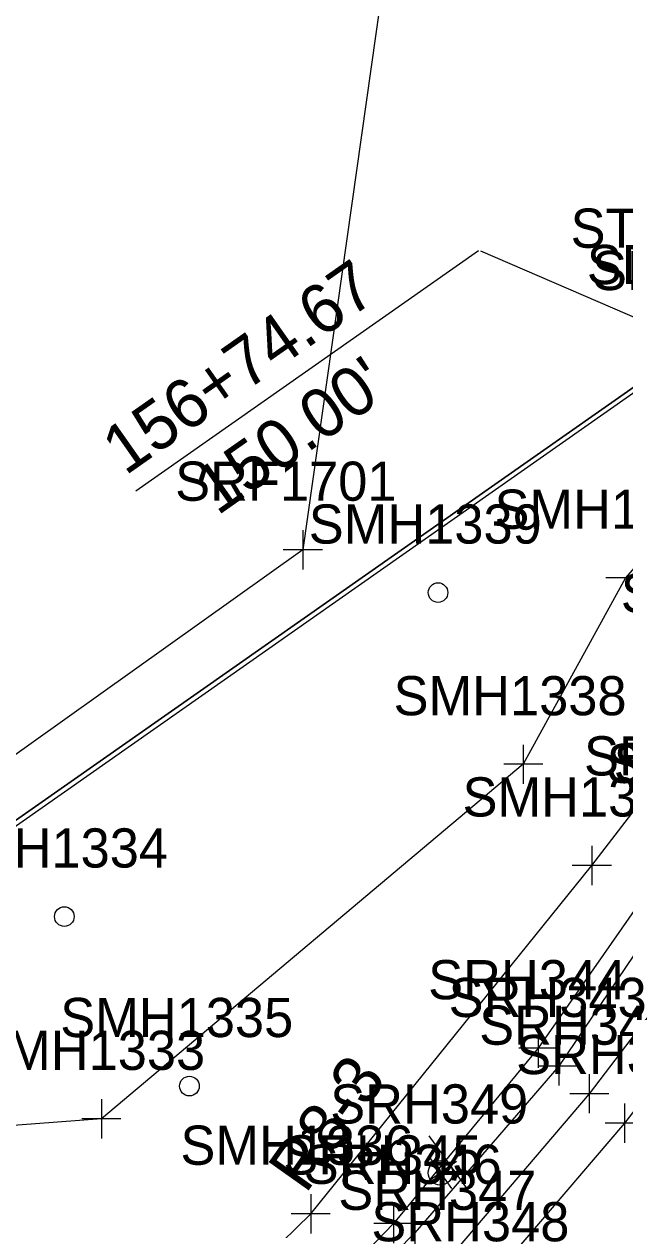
# Model space of a CAD drawing. Extents: x 941041 to 969446, y 397014 to 416764.
# Drawn here: x 951336.1 to 951397.4, y 403015.6 to 403138.7 of the extents above; entities that cross this region are included whole.
import ezdxf

# ---------------------------------------------------------------- set-up
doc = ezdxf.new("R2010")
doc.units = 0
for name, color, linetype in [('SURVEY - DRAINAGE - Area Shapes', 7, 'Continuous'), ('SURVEY - DRAINAGE - Area Shapes - Points - Locators', 7, 'Continuous'), ('SURVEY - DRAINAGE - Area Shapes - Points - Numbers', 7, 'Continuous'), ('SURVEY - DTM - Breaklines', 7, 'Continuous'), ('SURVEY - DTM - Breaklines - Points - Locators', 7, 'Continuous'), ('SURVEY - DTM - Breaklines - Points - Numbers', 7, 'Continuous'), ('SURVEY - DTM - Spot Points - Locators', 7, 'Continuous'), ('SURVEY - DTM - Spot Points - Point Numbers', 7, 'Continuous'), ('SURVEY - DTM GRAPHICS - Boundary Line', 7, 'Continuous'), ('SURVEY - NON-TRANSPORTATION - Features', 7, 'Continuous'), ('SURVEY - NON-TRANSPORTATION - Features - Points - Numbers', 7, 'Continuous'), ('SURVEY - PROPERTY - ROW Lines', 7, 'Continuous'), ('SURVEY - PROPERTY - ROW Markers - Points - Numbers', 7, 'Continuous'), ('SURVEY - PROPERTY - Station and Offset Flags', 7, 'Continuous'), ('SURVEY - TRAFFIC CONTROL - Pavement Marking - Points - Locators', 7, 'Continuous'), ('SURVEY - TRAFFIC CONTROL - Pavement Marking - Points - Numbers', 7, 'Continuous'), ('SURVEY - TRAFFIC CONTROL - Signs - Points - Locators', 7, 'Continuous'), ('SURVEY - TRAFFIC CONTROL - Signs - Points - Numbers', 7, 'Continuous'), ('SURVEY - TRAFFIC CONTROL - Signs and Devices with Text', 7, 'Continuous'), ('SURVEY - TRANSPORTATION - Features', 7, 'Continuous'), ('SURVEY - TRANSPORTATION - Features - Points - Locators', 7, 'Continuous'), ('SURVEY - TRANSPORTATION - Features - Points - Numbers', 7, 'Continuous'), ('SURVEY - TRANSPORTATION - Roads', 7, 'Continuous'), ('SURVEY - TRANSPORTATION - Roads - Points - Locators', 7, 'Continuous'), ('SURVEY - TRANSPORTATION - Roads - Points - Numbers', 7, 'Continuous'), ('SURVEY - UTILITIES - Poles and Miscellaneous - Points - Numbers', 7, 'Continuous'), ('SURVEY - VEGETATION - Features - Points - Locators', 7, 'Continuous'), ('SURVEY - VEGETATION - Features - Points - Numbers', 7, 'Continuous'), ('SURVEY - VEGETATION - Features with Text', 7, 'Continuous')]:
    doc.layers.add(name, color=color, linetype=linetype)

msp = doc.modelspace()

# ---------------------------------------------------------------- linework, layer by layer
at = {"layer": 'SURVEY - DRAINAGE - Area Shapes'}
for points in [[(951570.1, 403333.86), (951394.91, 403299.54), (951364.56, 403085.05), (950690.3, 402604.57), (950747.14, 402539.76)], [(950765.73, 402528.11), (951145.6, 402792.15), (951242.57, 402873.52), (951348.31, 402952.21), (951398.95, 403004.27), (951428.85, 403040.93), (951473.12, 403113.97), (951570.1, 403333.86), (951394.91, 403299.54), (951364.56, 403085.05), (950690.3, 402604.57), (950747.14, 402539.76), (950765.73, 402528.11)]]:
    msp.add_lwpolyline(points, dxfattribs=at)
at = {"layer": 'SURVEY - DRAINAGE - Area Shapes - Points - Locators'}
for p, q in [((951364.56, 403087.05), (951364.56, 403083.05)), ((951366.56, 403085.05), (951362.56, 403085.05))]:
    msp.add_line(p, q, dxfattribs=at)
at = {"layer": 'SURVEY - DTM - Breaklines'}
for points in [[(950944.44, 402708.35), (950986.6, 402737.09), (951031.98, 402767.67), (951074.18, 402796.92), (951116.54, 402825.71), (951158.8, 402855.37), (951201.22, 402884.32), (951244.36, 402916.65), (951286.66, 402946.54), (951324.24, 402977.13), (951365.36, 403017.29), (951394.06, 403052.83), (951410.05, 403073.63), (951458.13, 403162.28), (951483.55, 403213.16), (951504.25, 403257.1), (951548.43, 403354.82)], [(951404.5, 403057.02), (951388.59, 403034.18), (951373.81, 403016.3), (951353.68, 402995.42), (951325.73, 402969.82), (951296.63, 402946.16), (951268.96, 402924.9), (951228.2, 402894.58), (951186.77, 402863.94), (951145.14, 402834.63), (951106.17, 402807.78), (951067.06, 402780.74), (951027.03, 402752.5), (950987.44, 402723.92), (950948.21, 402695.85), (950901.61, 402662.26), (950863.92, 402634.17), (950821.87, 402602.73), (950781, 402573.02)]]:
    msp.add_lwpolyline(points, dxfattribs=at)
at = {"layer": 'SURVEY - DTM - Breaklines - Points - Locators'}
for p, q in [((951394.06, 403054.83), (951394.06, 403050.83)), ((951396.06, 403052.83), (951392.06, 403052.83)), ((951388.59, 403036.18), (951388.59, 403032.18)), ((951390.59, 403034.18), (951386.59, 403034.18)), ((951365.36, 403019.29), (951365.36, 403015.29)), ((951373.81, 403018.3), (951373.81, 403014.3)), ((951367.36, 403017.29), (951363.36, 403017.29)), ((951375.81, 403016.3), (951371.81, 403016.3))]:
    msp.add_line(p, q, dxfattribs=at)
at = {"layer": 'SURVEY - DTM - Spot Points - Locators'}
for centre in [(951378.36, 403080.68), (951340.21, 403047.62), (951352.98, 403030.32)]:
    msp.add_circle(centre, 1, dxfattribs=at)
at = {"layer": 'SURVEY - DTM GRAPHICS - Boundary Line'}
msp.add_lwpolyline([(951575.07, 404018.69), (951594.81, 403959.15), (951592.33, 403907.04), (951593.34, 403830.61), (951643.02, 403826.18), (951710.4, 403762.77), (951727.47, 403714.2), (951716.98, 403687.98), (951730.3, 403662.6), (951739.47, 403650.39), (951738.55, 403643.5), (951746.79, 403639.72), (951736.73, 403589.73), (951706.43, 403559.07), (951672.49, 403500.14), (951641.86, 403470.19), (951622.56, 403452.94), (951588.18, 403418.84), (951548.43, 403354.82), (951490.75, 403254.61), (951405.32, 403106.55), (950864.72, 402727.75)], dxfattribs=at)
at = {"layer": 'SURVEY - NON-TRANSPORTATION - Features'}
msp.add_lwpolyline([(950864.72, 402727.75), (951405.32, 403106.55), (951490.75, 403254.61), (951622.56, 403452.94), (951851.46, 403680.18), (951878.49, 403682.56)], dxfattribs=at)
at = {"layer": 'SURVEY - PROPERTY - ROW Lines'}
msp.add_line((951405.14, 403105.86), (950880.11, 402737.61), dxfattribs=at)
at = {"layer": 'SURVEY - PROPERTY - Station and Offset Flags'}
msp.add_line((951382.49, 403115.57), (951347.5, 403091.02), dxfattribs=at)
msp.add_lwpolyline([(951382.7, 403115.57), (951405.14, 403105.86)], dxfattribs=at)
at = {"layer": 'SURVEY - TRAFFIC CONTROL - Pavement Marking - Points - Locators'}
for p, q in [((951397.41, 403028.54), (951397.41, 403024.54)), ((951399.41, 403026.54), (951395.41, 403026.54))]:
    msp.add_line(p, q, dxfattribs=at)
at = {"layer": 'SURVEY - TRAFFIC CONTROL - Signs - Points - Locators'}
for p, q in [((951376.98, 403020.34), (951380.23, 403022.67)), ((951379.77, 403019.88), (951377.44, 403023.13))]:
    msp.add_line(p, q, dxfattribs=at)
at = {"layer": 'SURVEY - TRAFFIC CONTROL - Signs and Devices with Text'}
msp.add_line((951377.41, 403025.26), (951381.79, 403019.18), dxfattribs=at)
msp.add_circle((951378.6, 403021.47), 1.25, dxfattribs=at)
at = {"layer": 'SURVEY - TRANSPORTATION - Features'}
msp.add_lwpolyline([(951406.86, 403056.25), (951390.68, 403032.37), (951376, 403015.34), (951355.22, 402994.23), (951327.1, 402968.39), (951298.08, 402944.15), (951270.44, 402922.46), (951229.64, 402892.03), (951187.14, 402861.33), (951146.52, 402833.1), (951107.71, 402806.53), (951068.28, 402778.93), (951028.06, 402751.02), (950988.38, 402722.54), (950949, 402694.44), (950902.92, 402661.08), (950864.64, 402632.92), (950822.64, 402601.73), (950781.7, 402572.06), (950745.88, 402544.94), (950716.67, 402522.96)], dxfattribs=at)
at = {"layer": 'SURVEY - TRANSPORTATION - Features - Points - Locators'}
for p, q in [((951390.68, 403034.37), (951390.68, 403030.37)), ((951392.68, 403032.37), (951388.68, 403032.37)), ((951376, 403017.34), (951376, 403013.34))]:
    msp.add_line(p, q, dxfattribs=at)
at = {"layer": 'SURVEY - TRANSPORTATION - Roads'}
for points in [[(951410.7, 403051.7), (951393.8, 403029.54), (951379.42, 403012.69), (951359.06, 402991.46), (951330.74, 402964.31), (951301.59, 402939.74), (951273.95, 402918.57), (951232.23, 402888.27), (951188.46, 402857.67), (951149.32, 402830.16), (951110.42, 402802.41), (951071.27, 402775.13), (951030.97, 402746.68), (950990.91, 402718.7), (950951.71, 402691.24), (950905.16, 402658.93), (950866.67, 402631.07), (950824.58, 402600.25), (950783.31, 402570.16)], [(951414.76, 403048.91), (951397.41, 403026.54), (951382.84, 403009.48), (951362.61, 402987.81), (951333.74, 402960.2), (951304.6, 402935.06), (951276.51, 402913.06), (951235.4, 402883.45), (951192.72, 402853.54), (951151.98, 402824.99), (951113.28, 402797.96), (951074.6, 402770.69), (951034.02, 402742.32), (950993.7, 402714.11), (950954.4, 402686.24), (950909.08, 402652.74), (950870.89, 402623.6), (950829.23, 402591.97), (950787.49, 402560.18)]]:
    msp.add_lwpolyline(points, dxfattribs=at)
at = {"layer": 'SURVEY - TRANSPORTATION - Roads - Points - Locators'}
for p, q in [((951393.8, 403031.54), (951393.8, 403027.54)), ((951395.8, 403029.54), (951391.8, 403029.54))]:
    msp.add_line(p, q, dxfattribs=at)
at = {"layer": 'SURVEY - VEGETATION - Features - Points - Locators'}
for p, q in [((951399.48, 403082.19), (951395.48, 403082.19)), ((951387.06, 403065.16), (951387.06, 403061.16)), ((951389.06, 403063.16), (951385.06, 403063.16)), ((951343.99, 403028.97), (951343.99, 403024.97)), ((951345.99, 403026.97), (951341.99, 403026.97))]:
    msp.add_line(p, q, dxfattribs=at)
at = {"layer": 'SURVEY - VEGETATION - Features with Text'}
msp.add_lwpolyline([(951868.69, 403693.52), (951860.48, 403665.55), (951848.34, 403659.79), (951791.64, 403612.32), (951746.84, 403559.94), (951643.65, 403453.43), (951600.78, 403415.7), (951529.23, 403307.04), (951432.31, 403122.21), (951397.48, 403082.19), (951387.06, 403063.16), (951343.99, 403026.97), (951317.91, 403024.99), (951275.96, 402980.18), (951202.21, 402921.55), (951122.62, 402900.03), (951100.62, 402857.44), (951081.13, 402854.56), (950864.72, 402727.75), (951405.32, 403106.55), (951588.18, 403418.84), (951738.55, 403643.48), (951840.77, 403717.4), (951868.69, 403693.52)], dxfattribs=at)

# ---------------------------------------------------------------- texts
at = {"layer": 'SURVEY - DRAINAGE - Area Shapes - Points - Numbers'}
msp.add_text('SRF1701', height=4, dxfattribs=at).set_placement((951351.52, 403090.05))
at = {"layer": 'SURVEY - DTM - Breaklines - Points - Numbers'}
for s, p in [('SMH1341', (951397.02, 403078.63)), ('SRH337', (951393.26, 403062.02)), ('SMH1337', (951380.86, 403057.83)), ('SRH344', (951377.35, 403039.18)), ('SMH1336', (951352.06, 403022.29)), ('SRH345', (951362.57, 403021.3))]:
    msp.add_text(s, height=4, dxfattribs=at).set_placement(p)
at = {"layer": 'SURVEY - DTM - Spot Points - Point Numbers'}
for s, p in [('SMH1339', (951365.16, 403085.68)), ('SMH1334', (951327.01, 403052.62)), ('SMH1335', (951339.79, 403035.32))]:
    msp.add_text(s, height=4, dxfattribs=at).set_placement(p)
at = {"layer": 'SURVEY - NON-TRANSPORTATION - Features - Points - Numbers'}
msp.add_text('SDB767', height=4, dxfattribs=at).set_placement((951394.08, 403111.55))
at = {"layer": 'SURVEY - PROPERTY - ROW Markers - Points - Numbers'}
msp.add_text('SDB762', height=4, dxfattribs=at).set_placement((951393.55, 403112.16))
at = {"layer": 'SURVEY - PROPERTY - Station and Offset Flags'}
for s, p in [('156+74.67', (951346.43, 403092.56)), ("150.00'", (951355.83, 403088.47))]:
    msp.add_text(s, height=5, rotation=35.0456, dxfattribs=at).set_placement(p)
at = {"layer": 'SURVEY - TRAFFIC CONTROL - Pavement Marking - Points - Numbers'}
for s, p in [('SRH341', (951386.33, 403031.54)), ('SRH348', (951371.55, 403014.48))]:
    msp.add_text(s, height=4, dxfattribs=at).set_placement(p)
at = {"layer": 'SURVEY - TRAFFIC CONTROL - Signs - Points - Numbers'}
msp.add_text('SRH349', height=4, dxfattribs=at).set_placement((951367.35, 403026.5))
at = {"layer": 'SURVEY - TRAFFIC CONTROL - Signs and Devices with Text'}
msp.add_text('R8-3', height=5, rotation=54.7025, dxfattribs=at).set_placement((951364.84, 403019.23))
at = {"layer": 'SURVEY - TRANSPORTATION - Features - Points - Numbers'}
for s, p in [('SRH338', (951395.57, 403061.25)), ('SDB275', (951396.29, 403061.32)), ('SRH343', (951379.44, 403037.37)), ('SRH346', (951364.65, 403020.34))]:
    msp.add_text(s, height=4, dxfattribs=at).set_placement(p)
at = {"layer": 'SURVEY - TRANSPORTATION - Roads - Points - Numbers'}
for s, p in [('SRH342', (951382.56, 403034.54)), ('SRH347', (951368.18, 403017.69))]:
    msp.add_text(s, height=4, dxfattribs=at).set_placement(p)
at = {"layer": 'SURVEY - UTILITIES - Poles and Miscellaneous - Points - Numbers'}
msp.add_text('STB119', height=4, dxfattribs=at).set_placement((951391.89, 403115.87))
at = {"layer": 'SURVEY - VEGETATION - Features - Points - Numbers'}
for s, p in [('SMH1340', (951384.12, 403087.19)), ('SMH1338', (951373.82, 403068.16)), ('SMH1333', (951330.8, 403031.97))]:
    msp.add_text(s, height=4, dxfattribs=at).set_placement(p)

doc.saveas('drawing.dxf')
